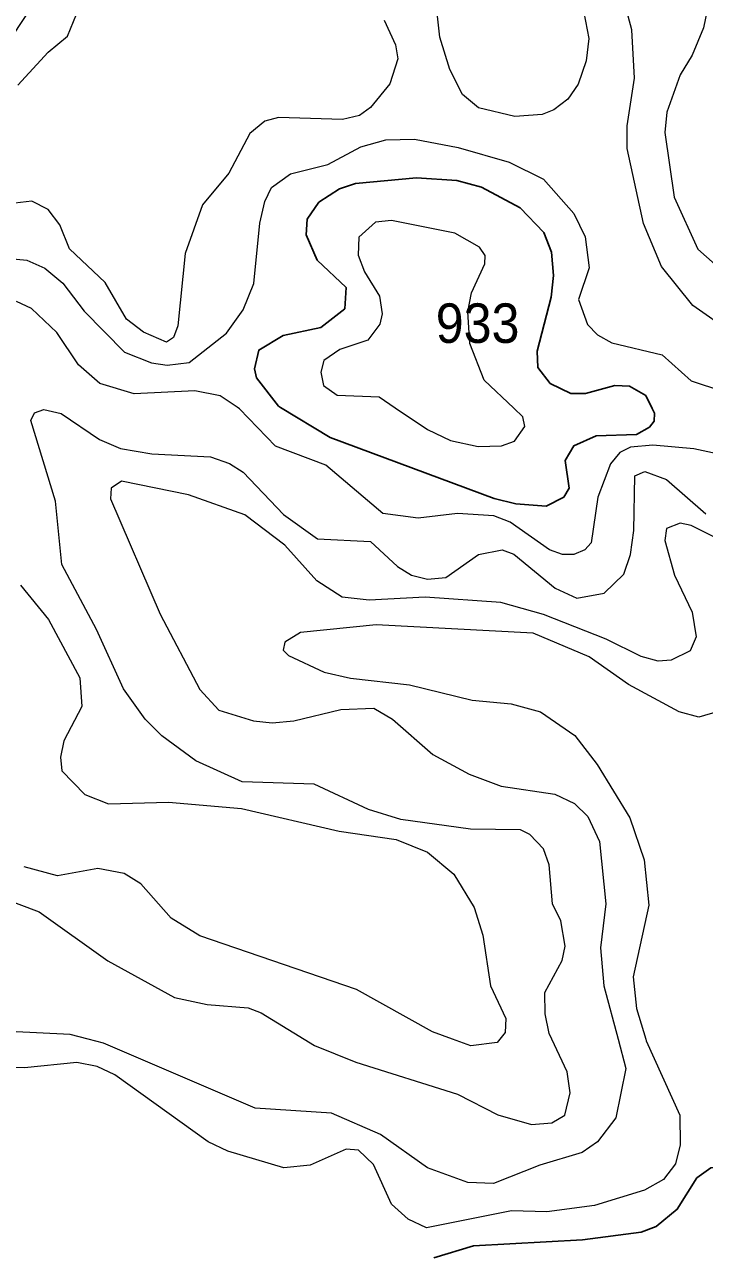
# Model space of a CAD drawing. Extents: x 473.9 to 500, y 7733.1 to 7760.8.
# Drawn here: x 491.19 to 492.567, y 7736.633 to 7739.125 of the extents above; entities that cross this region are included whole.
import ezdxf

# ---------------------------------------------------------------- set-up
doc = ezdxf.new("R2010")
doc.units = 0
doc.header["$LTSCALE"] = 0.032
doc.layers.add('1', color=7, linetype='Continuous', lineweight=25)
doc.layers.add('2', color=7, linetype='Continuous', lineweight=13)
doc.layers.add('21', color=7, linetype='Continuous')

msp = doc.modelspace()

# ---------------------------------------------------------------- linework, layer by layer
at = {"layer": '1'}
msp.add_lwpolyline([(492.2302, 7738.4298), (492.2285, 7738.4628), (492.2569, 7738.5727), (492.2616, 7738.6165), (492.2576, 7738.6635), (492.2419, 7738.7034), (492.1942, 7738.7536), (492.1159, 7738.7953), (492.0656, 7738.8091), (491.9839, 7738.814), (491.8608, 7738.8025), (491.8281, 7738.7923), (491.7863, 7738.7649), (491.7629, 7738.7305), (491.7604, 7738.699), (491.783, 7738.6473), (491.8418, 7738.592), (491.839, 7738.5492), (491.7907, 7738.5109), (491.714, 7738.4948), (491.6646, 7738.4653), (491.6557, 7738.4274), (491.6602, 7738.4089), (491.7046, 7738.3517), (491.7089, 7738.3491), (491.8096, 7738.2882), (492.1416, 7738.1644), (492.1854, 7738.1538), (492.2468, 7738.1491), (492.2823, 7738.167), (492.2935, 7738.1854), (492.2851, 7738.2419), (492.3025, 7738.2715), (492.3481, 7738.2917), (492.4296, 7738.2946), (492.4563, 7738.3093), (492.4657, 7738.3215), (492.4659, 7738.3374), (492.4614, 7738.3467), (492.4488, 7738.3732), (492.4158, 7738.3921), (492.3861, 7738.3937), (492.3267, 7738.3775), (492.2965, 7738.3775), (492.2549, 7738.3974)], close=True, dxfattribs=at)
msp.add_lwpolyline([(492.74, 7736.5495), (492.6941, 7736.6628), (492.6352, 7736.7367), (492.6092, 7736.7922), (492.5916, 7736.8095), (492.5806, 7736.8088), (492.552, 7736.7882), (492.5123, 7736.7246), (492.4698, 7736.6894), (492.4391, 7736.6783), (492.3203, 7736.6625), (492.0998, 7736.6505), (492.0193, 7736.6261)], dxfattribs=at)
at = {"layer": '2'}
for points in [[(492.0207, 7739.1978), (491.9935, 7739.254), (491.9845, 7739.3306), (491.987, 7739.3643), (492.0136, 7739.3884), (492.0559, 7739.396), (492.1283, 7739.3896), (492.183, 7739.3703), (492.2191, 7739.3414), (492.2952, 7739.2422), (492.3166, 7739.1849), (492.3334, 7739.0967), (492.3275, 7739.0514), (492.3116, 7739.004), (492.2904, 7738.9739), (492.2626, 7738.9523), (492.2387, 7738.9425), (492.183, 7738.9387), (492.1094, 7738.9561), (492.0772, 7738.9832), (492.0514, 7739.0337), (492.0317, 7739.0992)], [(492.0924, 7738.4789), (492.0881, 7738.5431), (492.0958, 7738.5814), (492.1228, 7738.6403), (492.1234, 7738.6567), (492.1118, 7738.6735), (492.0619, 7738.7023), (491.9337, 7738.7279), (491.9011, 7738.7245), (491.8672, 7738.6944), (491.8661, 7738.6575), (491.8786, 7738.6238), (491.9095, 7738.5743), (491.9143, 7738.539), (491.9102, 7738.5176), (491.8853, 7738.4854), (491.8287, 7738.4664), (491.7963, 7738.4442), (491.7906, 7738.4205), (491.7959, 7738.3933), (491.8237, 7738.3742), (491.9082, 7738.3706), (491.9412, 7738.3484), (492.0067, 7738.3042), (492.0532, 7738.2824), (492.109, 7738.2697), (492.1562, 7738.2711), (492.1823, 7738.2806), (492.2039, 7738.3106), (492.1995, 7738.33), (492.181, 7738.3476), (492.1215, 7738.4043)]]:
    msp.add_lwpolyline(points, close=True, dxfattribs=at)
for points in [[(492.6229, 7738.5001), (492.5436, 7738.5556), (492.4801, 7738.6344), (492.4439, 7738.7218), (492.4106, 7738.874), (492.4109, 7738.9195), (492.4258, 7739.0161), (492.42, 7739.1144), (492.3735, 7739.2883)], [(491.1769, 7739.0023), (491.2378, 7739.0692), (491.2775, 7739.1012), (491.3196, 7739.2062)], [(491.1995, 7739.1534), (491.1518, 7739.0809), (491.0996, 7739.033), (491.0529, 7739.0189), (490.9136, 7739.0198), (490.8806, 7739.0117), (490.8395, 7738.9812), (490.7655, 7738.8967), (490.7793, 7738.8734), (490.8915, 7738.8404), (490.93, 7738.8169), (490.9737, 7738.7796), (491.0349, 7738.6972), (491.0683, 7738.6669), (491.1035, 7738.6564), (491.1952, 7738.6472), (491.2315, 7738.6311), (491.268, 7738.6009), (491.3108, 7738.5444), (491.393, 7738.4614), (491.4471, 7738.4392), (491.479, 7738.4346), (491.5235, 7738.4404)], [(492.573, 7739.1543), (492.5657, 7739.118), (492.5428, 7739.0627), (492.5183, 7739.023), (492.4913, 7738.9475), (492.487, 7738.9061), (492.5057, 7738.7749), (492.5542, 7738.6698), (492.5893, 7738.639)], [(491.9189, 7739.1334), (491.9419, 7739.0836), (491.9466, 7739.0551), (491.9303, 7739.0048), (491.8907, 7738.9567), (491.8684, 7738.9407), (491.834, 7738.9322), (491.7049, 7738.9368), (491.6769, 7738.9288), (491.6464, 7738.9044), (491.604, 7738.8237), (491.5506, 7738.7598), (491.5155, 7738.6608), (491.501, 7738.5143), (491.4922, 7738.4908), (491.4776, 7738.4815), (491.4315, 7738.5017), (491.3971, 7738.5281), (491.3536, 7738.6022), (491.2813, 7738.6703), (491.2616, 7738.7191), (491.2382, 7738.7504), (491.2053, 7738.7672), (491.1474, 7738.7602)], [(491.5235, 7738.4404), (491.5996, 7738.4993), (491.633, 7738.5471), (491.6547, 7738.6002), (491.6669, 7738.7223), (491.6769, 7738.7662), (491.6906, 7738.7944), (491.7292, 7738.8225), (491.8047, 7738.841), (491.8716, 7738.8768), (491.9221, 7738.8912), (491.9803, 7738.8927), (492.0688, 7738.8758), (492.1721, 7738.8462), (492.2416, 7738.8115), (492.303, 7738.7417), (492.3261, 7738.6949), (492.3341, 7738.6322), (492.3124, 7738.5677), (492.3303, 7738.5171), (492.3507, 7738.4961), (492.3797, 7738.4801), (492.4817, 7738.4559), (492.5407, 7738.4032), (492.6042, 7738.3818)], [(492.7639, 7738.2183), (492.5459, 7738.2649), (492.463, 7738.2729), (492.4178, 7738.2687), (492.3958, 7738.2575), (492.3773, 7738.2346), (492.3517, 7738.167), (492.3376, 7738.0746), (492.3252, 7738.0608), (492.3029, 7738.051), (492.2799, 7738.0513), (492.2534, 7738.0607), (492.1738, 7738.1165), (492.1411, 7738.1297), (492.0672, 7738.1345), (491.9872, 7738.125), (491.9161, 7738.1339), (491.8002, 7738.2318), (491.6985, 7738.2709), (491.6255, 7738.3464), (491.6211, 7738.3494), (491.5864, 7738.3725), (491.5349, 7738.383), (491.4123, 7738.3764), (491.3425, 7738.3973), (491.2994, 7738.4352), (491.2559, 7738.5012), (491.2045, 7738.5497), (491.1743, 7738.5636)], [(492.2847, 7736.9154), (492.2956, 7736.9605), (492.2893, 7737.0028), (492.2584, 7737.0693), (492.2531, 7737.0806), (492.2446, 7737.1205), (492.2443, 7737.164), (492.2793, 7737.2287), (492.2852, 7737.2574), (492.2762, 7737.3088), (492.2594, 7737.3436), (492.253, 7737.4226), (492.2411, 7737.4548), (492.214, 7737.4837), (492.1948, 7737.4935), (492.0934, 7737.4947), (491.9525, 7737.5145), (491.8872, 7737.5348), (491.7771, 7737.5855), (491.6312, 7737.5903), (491.5375, 7737.6331), (491.4683, 7737.6836), (491.4343, 7737.7177), (491.3909, 7737.779), (491.3363, 7737.899), (491.2658, 7738.0309), (491.2527, 7738.1595), (491.2029, 7738.3227), (491.2103, 7738.338), (491.2294, 7738.3451), (491.2643, 7738.3367), (491.3422, 7738.2843), (491.3849, 7738.2662), (491.4481, 7738.2552), (491.5666, 7738.2488), (491.6057, 7738.2358), (491.633, 7738.2181), (491.7146, 7738.1325), (491.7837, 7738.0832), (491.8911, 7738.0776), (491.9459, 7738.0271), (491.9738, 7738.0094), (492.0061, 7738.0012), (492.0436, 7738.0047), (492.1096, 7738.0511), (492.1578, 7738.0605), (492.1813, 7738.052), (492.2653, 7737.9827), (492.309, 7737.9626), (492.3642, 7737.9727), (492.404, 7738.0115), (492.4174, 7738.0512), (492.4241, 7738.1), (492.4262, 7738.2108), (492.4463, 7738.2195), (492.4902, 7738.2032), (492.5701, 7738.1333)], [(491.3866, 7738.1995), (491.3658, 7738.1854), (491.3647, 7738.164), (491.4648, 7737.9301), (491.5453, 7737.7774), (491.5838, 7737.7358), (491.6541, 7737.7139), (491.692, 7737.71), (491.736, 7737.7144), (491.8309, 7737.7374), (491.8978, 7737.7398), (491.9354, 7737.7176), (492.0169, 7737.6461), (492.0908, 7737.6058), (492.1558, 7737.5821), (492.2645, 7737.5655), (492.3041, 7737.5464), (492.3309, 7737.5203), (492.355, 7737.4696), (492.3679, 7737.3437), (492.3566, 7737.2545), (492.3637, 7737.1773), (492.3923, 7737.0693), (492.408, 7737.0099), (492.3878, 7736.9101), (492.3506, 7736.8615), (492.32, 7736.8395), (492.2339, 7736.8139), (492.14, 7736.777), (492.0884, 7736.7787), (492.0067, 7736.8085), (491.9112, 7736.8763), (491.812, 7736.9193), (491.6572, 7736.9294), (491.3501, 7737.0612), (491.3193, 7737.0693), (491.2825, 7737.0789), (491.16, 7737.085)], [(492.6318, 7738.064), (492.5405, 7738.1102), (492.5184, 7738.1147), (492.4904, 7738.1037), (492.487, 7738.0793), (492.5066, 7738.0094), (492.5423, 7737.9344), (492.5504, 7737.8846), (492.5381, 7737.8558), (492.5002, 7737.8368), (492.4736, 7737.8353), (492.439, 7737.8445), (492.368, 7737.8796), (492.2414, 7737.9293), (492.1551, 7737.9542), (492.0019, 7737.9649), (491.8883, 7737.9585), (491.8335, 7737.9645), (491.7826, 7737.998), (491.7174, 7738.0702), (491.6362, 7738.1314), (491.5221, 7738.1723), (491.3866, 7738.1995)], [(491.1822, 7737.9887), (491.2385, 7737.9194), (491.3022, 7737.8014), (491.3066, 7737.743), (491.27, 7737.6738), (491.263, 7737.6405), (491.2661, 7737.6127), (491.3127, 7737.5651), (491.3602, 7737.546), (491.4818, 7737.5493)], [(492.5952, 7737.7329), (492.556, 7737.7214), (492.5164, 7737.7323), (492.4136, 7737.7877), (492.3342, 7737.8435), (492.2206, 7737.8918), (491.9027, 7737.9086), (491.7489, 7737.8932), (491.7175, 7737.8736), (491.7143, 7737.8575), (491.7252, 7737.8464), (491.797, 7737.813), (491.8506, 7737.8003), (491.9697, 7737.7871), (492.0967, 7737.7562), (492.176, 7737.7487), (492.235, 7737.7323), (492.3045, 7737.6843), (492.3501, 7737.6256), (492.4161, 7737.5179), (492.4451, 7737.4326), (492.4547, 7737.3405), (492.4232, 7737.1953), (492.4299, 7737.1314), (492.4484, 7737.0693), (492.4493, 7737.0661), (492.5176, 7736.9149), (492.5181, 7736.8554), (492.5084, 7736.8163), (492.4845, 7736.7847), (492.4462, 7736.7635), (492.3444, 7736.7322), (492.2484, 7736.7196), (492.1765, 7736.7211), (492.0045, 7736.6867), (491.9674, 7736.7042), (491.9336, 7736.7349), (491.8971, 7736.8155), (491.8667, 7736.844), (491.8414, 7736.846), (491.7687, 7736.8137)], [(491.4818, 7737.5493), (491.6296, 7737.5367), (491.8275, 7737.4904), (491.9428, 7737.4737), (492.0066, 7737.4478), (492.0599, 7737.4037), (492.1012, 7737.3357), (492.1186, 7737.2799), (492.1343, 7737.1775), (492.1651, 7737.111), (492.1636, 7737.0824), (492.1531, 7737.0693), (492.1475, 7737.0622), (492.0945, 7737.0556), (492.0573, 7737.0693), (492.0163, 7737.0843), (491.8625, 7737.17), (491.545, 7737.2788), (491.4873, 7737.3146), (491.4256, 7737.3836), (491.3918, 7737.4045), (491.3389, 7737.415), (491.2572, 7737.3998), (491.1894, 7737.4182)], [(491.1313, 7737.3603), (491.2202, 7737.327), (491.359, 7737.2278), (491.4938, 7737.1533), (491.5601, 7737.1393), (491.6432, 7737.1325), (491.6693, 7737.1224), (491.7564, 7737.0693), (491.7773, 7737.0565), (491.8614, 7737.0228), (492.0672, 7736.9575), (492.1488, 7736.916), (492.2168, 7736.8965), (492.258, 7736.8995), (492.2847, 7736.9154)], [(491.7687, 7736.8137), (491.7156, 7736.8087), (491.602, 7736.842), (491.5624, 7736.8611), (491.3734, 7736.9972), (491.3377, 7737.0141), (491.2959, 7737.0219), (491.1904, 7737.0114), (491.0931, 7737.0144)]]:
    msp.add_lwpolyline(points, dxfattribs=at)

# ---------------------------------------------------------------- texts
at = {"layer": '21', "width": 0.95}
msp.add_text('933', height=0.08, dxfattribs=at).set_placement((492.0231, 7738.4799))

doc.saveas('drawing.dxf')
